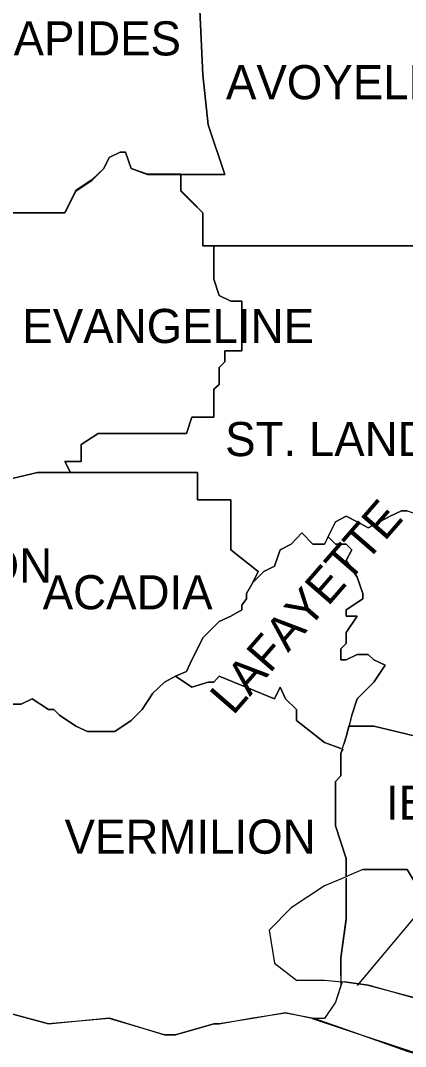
# Model space of a CAD drawing. Extents: x 0.23 to 2.82, y 0.04 to 1.79.
# Drawn here: x 2.3204 to 2.3732, y 1.4533 to 1.594 of the extents above; entities that cross this region are included whole.
import ezdxf

# ---------------------------------------------------------------- set-up
doc = ezdxf.new("R2010")
doc.units = 0
for name, color, linetype in [('Dist03', 7, 'Continuous'), ('Dist08', 7, 'Continuous'), ('Standard Info', 7, 'Continuous')]:
    doc.layers.add(name, color=color, linetype=linetype)

msp = doc.modelspace()

# ---------------------------------------------------------------- linework, layer by layer
at = {"layer": 'Dist03'}
for points in [[(2.3469, 1.56308), (2.3454, 1.56308), (2.3454, 1.56758), (2.3439, 1.56917), (2.3424, 1.57067), (2.3424, 1.57292), (2.34015, 1.57292), (2.33782, 1.57292), (2.33557, 1.57367), (2.33482, 1.57592), (2.33407, 1.57592), (2.33257, 1.57517), (2.33182, 1.57367), (2.33024, 1.57217), (2.32799, 1.57067), (2.32649, 1.56758), (2.31899, 1.56758)], [(2.37715, 1.56308), (2.3469, 1.56308)], [(2.36732, 1.47758), (2.3734, 1.47758), (2.37565, 1.47383), (2.37682, 1.47317)], [(2.36432, 1.463), (2.36432, 1.4655), (2.36507, 1.47083), (2.36507, 1.47608), (2.36507, 1.47625)], [(2.36049, 1.45725), (2.36507, 1.45567), (2.3734, 1.45267), (2.37865, 1.45117), (2.38015, 1.45117), (2.38324, 1.45267), (2.38324, 1.45642), (2.37949, 1.45875), (2.3764, 1.45942), (2.36807, 1.46175), (2.36482, 1.46217)], [(2.31815, 1.45808), (2.32424, 1.45642), (2.33257, 1.45725), (2.34015, 1.45492), (2.34165, 1.45492), (2.3469, 1.45642), (2.34765, 1.45642)], [(2.34765, 1.45642), (2.35224, 1.45725), (2.35674, 1.45792), (2.3604, 1.45725)]]:
    msp.add_lwpolyline(points, dxfattribs=at)
at = {"layer": 'Dist08'}
for points in [[(2.30232, 1.56758), (2.32649, 1.56758), (2.32799, 1.57067), (2.33024, 1.57217), (2.33182, 1.57367), (2.33257, 1.57517), (2.33407, 1.57592), (2.33482, 1.57592), (2.33557, 1.57367), (2.33782, 1.57292), (2.34015, 1.57292), (2.3424, 1.57292)], [(2.3424, 1.57292), (2.3424, 1.57067), (2.3439, 1.56917), (2.3454, 1.56758), (2.3454, 1.56308), (2.3764, 1.56308)]]:
    msp.add_lwpolyline(points, dxfattribs=at)
at = {"layer": 'Standard Info'}
msp.add_line((2.3654, 1.47675), (2.36507, 1.47658), dxfattribs=at)
for points in [[(2.35815, 1.605), (2.35374, 1.60233), (2.35224, 1.60158), (2.35074, 1.60158), (2.3499, 1.60158), (2.3484, 1.60392), (2.3469, 1.60392), (2.3454, 1.60233), (2.34465, 1.60233), (2.3454, 1.5865), (2.34615, 1.57967), (2.3484, 1.57283), (2.3424, 1.57283)], [(2.3424, 1.57283), (2.3484, 1.57283), (2.34615, 1.57967), (2.3454, 1.5865), (2.34465, 1.60233), (2.3454, 1.60233), (2.3469, 1.60392), (2.3484, 1.60392), (2.3499, 1.60158), (2.35074, 1.60158), (2.35224, 1.60158), (2.35374, 1.60233), (2.35815, 1.605)], [(2.3424, 1.57283), (2.34015, 1.57283), (2.33782, 1.57283), (2.33557, 1.57367), (2.33482, 1.57592), (2.33407, 1.57592), (2.33257, 1.57517), (2.33182, 1.57367), (2.33024, 1.57208), (2.32799, 1.57058), (2.32649, 1.56758), (2.30232, 1.56758)], [(2.31899, 1.56758), (2.32649, 1.56758), (2.32799, 1.57058), (2.33024, 1.57208), (2.33182, 1.57367), (2.33257, 1.57517), (2.33407, 1.57592), (2.33482, 1.57592), (2.33557, 1.57367), (2.33782, 1.57283), (2.34015, 1.57283), (2.3424, 1.57283), (2.3424, 1.57058), (2.3439, 1.56908), (2.3454, 1.56758), (2.3454, 1.56308), (2.3469, 1.56308)], [(2.3764, 1.56308), (2.3454, 1.56308), (2.3454, 1.56758), (2.3439, 1.56908), (2.3424, 1.57058), (2.3424, 1.57283)], [(2.3469, 1.56308), (2.3469, 1.5585), (2.34765, 1.55625), (2.34924, 1.5555), (2.35074, 1.5555), (2.35074, 1.54867), (2.3484, 1.54867), (2.3484, 1.54717), (2.34765, 1.54642), (2.34765, 1.54408), (2.3469, 1.54342), (2.3469, 1.53958), (2.3439, 1.53958), (2.34315, 1.53733), (2.33107, 1.53733), (2.32874, 1.53583), (2.32874, 1.5335), (2.32649, 1.5335), (2.32724, 1.532)], [(2.32724, 1.532), (2.32649, 1.5335), (2.32874, 1.5335), (2.32874, 1.53583), (2.33107, 1.53733), (2.34315, 1.53733), (2.3439, 1.53958), (2.3469, 1.53958), (2.3469, 1.54342), (2.34765, 1.54408), (2.34765, 1.54642), (2.3484, 1.54717), (2.3484, 1.54867), (2.35074, 1.54867), (2.35074, 1.5555), (2.34924, 1.5555), (2.34765, 1.55625), (2.3469, 1.5585), (2.3469, 1.56308)], [(2.3469, 1.56308), (2.37715, 1.56308)], [(2.36257, 1.52317), (2.36357, 1.52525), (2.36507, 1.526), (2.36657, 1.52525), (2.36807, 1.52442), (2.37107, 1.526), (2.37265, 1.52675), (2.3734, 1.52675), (2.37565, 1.526), (2.37715, 1.52525), (2.38624, 1.52525), (2.38624, 1.52675), (2.38549, 1.5275), (2.38324, 1.52975), (2.38324, 1.5305), (2.38249, 1.532), (2.38015, 1.53433), (2.38299, 1.53617)], [(2.32724, 1.532), (2.32274, 1.532), (2.31749, 1.53075)], [(2.31749, 1.53075), (2.32274, 1.532), (2.32799, 1.532), (2.34465, 1.532), (2.34465, 1.52825), (2.34924, 1.52825), (2.34924, 1.52142), (2.35299, 1.51842), (2.35224, 1.51692)], [(2.35224, 1.51692), (2.35299, 1.51842), (2.34924, 1.52142), (2.34924, 1.52825), (2.34465, 1.52825), (2.34465, 1.532), (2.32724, 1.532)], [(2.3734, 1.52675), (2.37265, 1.52675), (2.37107, 1.526), (2.36807, 1.52442), (2.36657, 1.52525), (2.36507, 1.526), (2.36357, 1.52525), (2.36282, 1.52375), (2.36207, 1.52217), (2.36049, 1.52217), (2.35899, 1.52375), (2.35749, 1.52217), (2.35599, 1.52142), (2.35524, 1.51917), (2.35374, 1.51842), (2.35224, 1.51692)], [(2.34165, 1.50408), (2.34315, 1.50475), (2.3439, 1.50633), (2.34465, 1.50783), (2.3454, 1.50933), (2.34615, 1.51008), (2.34765, 1.51158), (2.34924, 1.51233), (2.35074, 1.51317), (2.35074, 1.51383), (2.3514, 1.51467), (2.3514, 1.51542), (2.35224, 1.51692), (2.35374, 1.51842), (2.35524, 1.51917), (2.35599, 1.52142), (2.35749, 1.52217), (2.35899, 1.52375), (2.36049, 1.52217), (2.36207, 1.52217), (2.36257, 1.52317)], [(2.36257, 1.52317), (2.36357, 1.52217), (2.36507, 1.52217), (2.36582, 1.52142), (2.36507, 1.51992), (2.36657, 1.51767), (2.36732, 1.51542), (2.36732, 1.51467), (2.36507, 1.51317), (2.36507, 1.51233), (2.36657, 1.51233), (2.36507, 1.51008), (2.36507, 1.50858), (2.36432, 1.50783), (2.36432, 1.50633), (2.36507, 1.50633), (2.36657, 1.50708), (2.36807, 1.50708), (2.36882, 1.50633), (2.3704, 1.50558), (2.36882, 1.50325), (2.36657, 1.501), (2.36582, 1.49875), (2.36507, 1.49575), (2.36474, 1.49475)], [(2.36549, 1.49725), (2.36582, 1.49875), (2.36657, 1.501), (2.36882, 1.50325), (2.3704, 1.50558), (2.36882, 1.50633), (2.36807, 1.50708), (2.36657, 1.50708), (2.36507, 1.50633), (2.36432, 1.50633), (2.36432, 1.50783), (2.36507, 1.50858), (2.36507, 1.51008), (2.36657, 1.51233), (2.36507, 1.51233), (2.36507, 1.51317), (2.36732, 1.51467), (2.36732, 1.51542), (2.36657, 1.51767), (2.36507, 1.51992), (2.36582, 1.52142), (2.36507, 1.52217), (2.36357, 1.52217), (2.36257, 1.52317)], [(2.35224, 1.51692), (2.3514, 1.51542), (2.3514, 1.51467), (2.35074, 1.51383), (2.35074, 1.51317), (2.34924, 1.51233), (2.34765, 1.51158), (2.34615, 1.51008), (2.3454, 1.50933), (2.34465, 1.50783), (2.3439, 1.50633), (2.34315, 1.50475), (2.34165, 1.50408), (2.34015, 1.50325), (2.33857, 1.50175), (2.33707, 1.4995), (2.33632, 1.49875), (2.33557, 1.498), (2.33332, 1.4965), (2.33182, 1.4965), (2.32957, 1.4965), (2.32799, 1.49725), (2.32574, 1.49875), (2.32499, 1.4995), (2.32424, 1.4995), (2.32199, 1.501), (2.32049, 1.50025), (2.31765, 1.50025)], [(2.31765, 1.50025), (2.32049, 1.50025), (2.32199, 1.501), (2.32424, 1.4995), (2.32499, 1.4995), (2.32574, 1.49875), (2.32799, 1.49725), (2.32957, 1.4965), (2.33182, 1.4965), (2.33332, 1.4965), (2.33557, 1.498), (2.33632, 1.49875), (2.33707, 1.4995), (2.33857, 1.50175), (2.34015, 1.50325), (2.34165, 1.50408)], [(2.34165, 1.50408), (2.3439, 1.50258), (2.34615, 1.50325), (2.3469, 1.50325), (2.34765, 1.50408), (2.35524, 1.501), (2.35599, 1.50258), (2.35674, 1.501), (2.35824, 1.4995), (2.35824, 1.498), (2.36207, 1.495), (2.36432, 1.49417)], [(2.36432, 1.49417), (2.36207, 1.495), (2.35824, 1.498), (2.35824, 1.4995), (2.35674, 1.501), (2.35599, 1.50258), (2.35524, 1.501), (2.34765, 1.50408), (2.3469, 1.50325), (2.34615, 1.50325), (2.3439, 1.50258), (2.34165, 1.50408)], [(2.36549, 1.49725), (2.36882, 1.49725), (2.3719, 1.4965), (2.3749, 1.49575), (2.3764, 1.49575), (2.3779, 1.49725), (2.37865, 1.498), (2.37949, 1.50025), (2.38099, 1.50175), (2.38399, 1.50258), (2.38699, 1.50175), (2.38849, 1.4995), (2.38924, 1.498), (2.39157, 1.49725), (2.39232, 1.495), (2.39982, 1.495), (2.39982, 1.49725), (2.40665, 1.4965), (2.40974, 1.49725)], [(2.40974, 1.49725), (2.40665, 1.4965), (2.39982, 1.49725), (2.39982, 1.495), (2.39232, 1.495), (2.39157, 1.49725), (2.38924, 1.498), (2.38849, 1.4995), (2.38699, 1.50175), (2.38399, 1.50258), (2.38099, 1.50175), (2.37949, 1.50025), (2.37865, 1.498), (2.3779, 1.49725), (2.3764, 1.49575), (2.3749, 1.49575), (2.3719, 1.4965), (2.36882, 1.49725), (2.36549, 1.49725)], [(2.36507, 1.47658), (2.36507, 1.47908), (2.36357, 1.48358), (2.36357, 1.48967), (2.36432, 1.49042), (2.36432, 1.4935), (2.36507, 1.49575), (2.3654, 1.49725)], [(2.36457, 1.49408), (2.36432, 1.4935), (2.36432, 1.49042), (2.36357, 1.48967), (2.36357, 1.48358), (2.36507, 1.47908), (2.36507, 1.47658)], [(2.36732, 1.47758), (2.3654, 1.47675)], [(2.36732, 1.47758), (2.3654, 1.47675)], [(2.37682, 1.47308), (2.37565, 1.47383), (2.3734, 1.47758), (2.36732, 1.47758)], [(2.37682, 1.47308), (2.37565, 1.47383), (2.3734, 1.47758), (2.36732, 1.47758)], [(2.36507, 1.47658), (2.36207, 1.47533), (2.35749, 1.47233), (2.35449, 1.46925), (2.35524, 1.46475), (2.35824, 1.46242), (2.36207, 1.46242), (2.36449, 1.46217)], [(2.36507, 1.47642), (2.36507, 1.47608), (2.36507, 1.47075), (2.36432, 1.4655), (2.36432, 1.46167), (2.36357, 1.45942), (2.36207, 1.45717), (2.3604, 1.45717)], [(2.3769, 1.47325), (2.37415, 1.47075), (2.36657, 1.46167)], [(2.3604, 1.45717), (2.37865, 1.45108), (2.38015, 1.45108), (2.38324, 1.45267), (2.38324, 1.45642), (2.37949, 1.45867), (2.36807, 1.46167), (2.36449, 1.46217)], [(2.36449, 1.46217), (2.36357, 1.45942), (2.36207, 1.45717), (2.36132, 1.45717)], [(2.34765, 1.45642), (2.3469, 1.45642), (2.34165, 1.45492), (2.34015, 1.45492), (2.33257, 1.45717), (2.32424, 1.45642), (2.31815, 1.45808)], [(2.3604, 1.45717), (2.35674, 1.45792), (2.35224, 1.45717), (2.34765, 1.45642)]]:
    msp.add_lwpolyline(points, dxfattribs=at)

# ---------------------------------------------------------------- texts
for s, p in [('RAPIDES', (2.31494, 1.58917)), ('AVOYELLES', (2.34857, 1.58317)), ('EVANGELINE', (2.32066, 1.54975)), ('ST. LANDRY', (2.34846, 1.53425)), ('JEFFERSON', (2.28754, 1.51692)), ('ACADIA', (2.32345, 1.51325)), ('IBERIA', (2.37051, 1.48442)), ('VERMILION', (2.32645, 1.47975))]:
    msp.add_text(s, height=0.004679, dxfattribs=at).set_placement(p)
for s, height, rotation, p in [('LAFAYETTE', 0.004679, 48.9999, (2.34955, 1.49859)), ('G U L F   O F   M E X I C O', 0.0062, 345.6507, (2.26182, 1.4493))]:
    msp.add_text(s, height=height, rotation=rotation, dxfattribs=at).set_placement(p)

doc.saveas('drawing.dxf')
